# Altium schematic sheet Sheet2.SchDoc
size A4
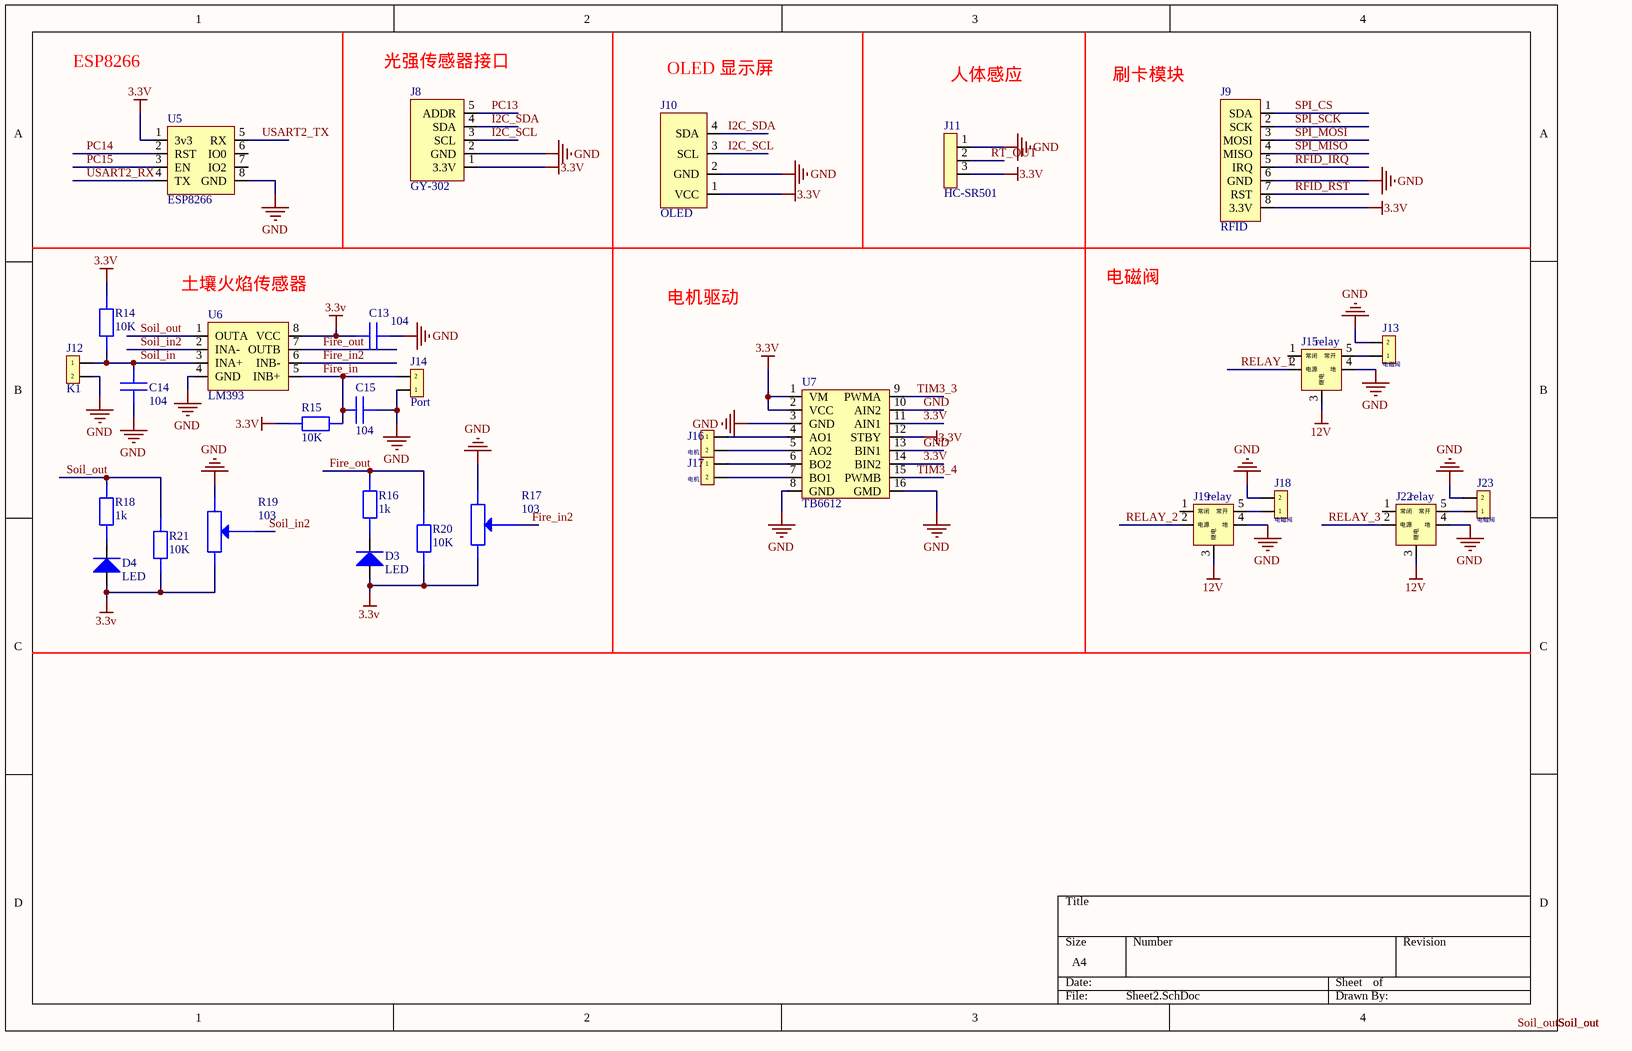
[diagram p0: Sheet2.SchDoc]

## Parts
C13  104  [CAP_0603_FIRE]
C14  104  [CAP_0603_FIRE]
C15  104  [CAP_0603_FIRE]
D3  LED  [LED_Z]
D4  LED  [LED_Z]
J8  GY-302  [GY]
J9  RFID  [RFID]
J10  OLED  [OLED]
J11  HC-SR501  [HDR1X3]
J12  K1  [port_2]
J13  电磁阀  [port_2]
J14  Port  [port_2]
J15  relay  [relay]
J16  电机  [port_2]
J17  电机  [port_2]
J18  电磁阀  [port_2]
J19  relay  [relay]
J22  relay  [relay]
J23  电磁阀  [port_2]
R14  10K  [R_0603]
R15  10K  [R_0603]
R16  1k  [R_0603]
R17  103  [RES_R]
R18  1k  [R_0603]
R19  103  [RES_R]
R20  10K  [R_0603]
R21  10K  [R_0603]
U5  ESP8266  [ESP8266]
U6  LM393  [LM393]
U7  TB6612  [TB6612]

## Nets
3.3V: C13.1 D3.1 D4.1 J8.1(3.3V) J9.8(3.3V) J10.1(VCC) J11.3 R14.2 R15.1 R17.2(VCC) R19.2(VCC) R20.1 R21.1 U5.1(3v3) U6.8(VCC) U7.1(VM) U7.2(VCC) U7.11(AIN1) U7.12(STBY) U7.14(BIN2)
12V: J15.3(继电) J19.3(继电) J22.3(继电)
GND: C13.2 C14.1 C15.2 J8.2(GND) J9.6(GND) J10.2(GND) J11.1 J12.2 J13.2 J14.1 J15.4(地) J18.2 J19.4(地) J22.4(地) J23.2 R17.1(VCC) R19.1(VCC) U5.8(GND) U6.4(GND) U7.3(GND) U7.8(GND) U7.10(AIN2) U7.13(BIN1) U7.16(GMD)
Fire_in: C15.1 J14.2 R15.2 U6.5(INB+)
Fire_in2: R17.3(VCC) U6.6(INB-)
Fire_out: R16.2 R20.2 U6.7(OUTB)
I2C_SCL: J8.3(SCL) J10.3(SCL)
I2C_SDA: J8.4(SDA) J10.4(SDA)
PC13: J8.5(ADDR)
PC14: U5.2(RST)
PC15: U5.3(EN)
RELAY_1: J15.2(电源)
RELAY_2: J19.2(电源)
RELAY_3: J22.2(电源)
RFID_IRQ: J9.5(IRQ)
RFID_RST: J9.7(RST)
RT_OUT: J11.2
Soil_in: C14.2 J12.1 R14.1 U6.3(INA+)
Soil_in2: R19.3(VCC) U6.2(INA-)
Soil_out: R18.2 R21.2 U6.1(OUTA)
SPI_CS: J9.1(SDA)
SPI_MISO: J9.4(MISO)
SPI_MOSI: J9.3(MOSI)
SPI_SCK: J9.2(SCK)
TIM3_3: U7.9(PWMA)
TIM3_4: U7.15(PWMB)
USART2_RX: U5.4(TX)
USART2_TX: U5.5(RX)
NetD3_2: D3.2 R16.1
NetD4_2: D4.2 R18.1
NetJ13_1: J13.1 J15.5(常开)
NetJ16_1: J16.1 U7.4(AO1)
NetJ16_2: J16.2 U7.5(AO2)
NetJ17_1: J17.1 U7.6(BO2)
NetJ17_2: J17.2 U7.7(BO1)
NetJ18_1: J18.1 J19.5(常开)
NetJ22_5: J22.5(常开) J23.1

Not connected (* = marked no-connect by the designer): J15 1(常闭); J19 1(常闭); J22 1(常闭); U5 6(IO0) 7(IO2)

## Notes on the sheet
- ESP8266
- (near J8) 光强传感器接口
- OLED 显示屏
- 人体感应
- 刷卡模块
- (near U6) 土壤火焰传感器
- 电机驱动
- 电磁阀
- Labels drawn without touching a wire or pin: Soil_out

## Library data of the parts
C13-C15 = Capacitance
J12 J13 J16-J18 J23 = port_2
R14-R16 R18 R20 R21 = RES
R17 R19 = RES_R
